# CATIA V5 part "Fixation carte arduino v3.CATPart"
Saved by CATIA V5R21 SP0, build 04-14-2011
Part number: Porte carte arduino
Bounding box of the stored display mesh (mm): x -6.9 to 25, y 0 to 105, z 0 to 59.3
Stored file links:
  C:\Users\2027.DESARCY-LEMIE30\Desktop\V16(05.04.2023)\Fixation carte arduino v3.CATPart
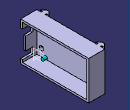
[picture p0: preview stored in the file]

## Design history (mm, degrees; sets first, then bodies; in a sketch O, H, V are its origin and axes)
Body1 (main body)
  Sketch1 on yz-plane, origin (0, 0, 0), H (0, 1, 0), V (0, 0, 1)
    line L1 (0, 0) -> (105, 0)
    line L2 (105, 0) -> (105, 59.3)
    line L3 (105, 59.3) -> (0, 59.3)
    line L4 (0, 59.3) -> (0, 0)
    length L3 = 105
    length L2 = 59.3
    horizontal: L1 H, L3 H
    vertical: L2 V, L4 V
  Pad1: profile Sketch1, direction (1, 0, 0), length 20
  Sketch2 on end face of Pad1, origin (20, 0, 0), H (0, 1, 0), V (0, 0, 1)
    line L1 (3, 3) -> (102, 3)
    line L2 (102, 3) -> (102, 56.3)
    line L3 (102, 56.3) -> (3, 56.3)
    line L4 (3, 56.3) -> (3, 3)
    reference projected line E1 (105, 0) -> (105, 59) from edge [face of Pad1 from Sketch1.L2 | end face of Pad1]
    reference projected line E2 (108.5, 59.3) -> (0, 59.3) from edge [face of Pad1 from Sketch1.L3 | end face of Pad1]
    reference projected line E3 (0, 59.3) -> (0, 0) from edge [face of Pad1 from Sketch1.L4 | end face of Pad1]
    reference projected line E4 (0, 0) -> (105, 0) from edge [face of Pad1 from Sketch1.L1 | end face of Pad1]
    distance L2 E1 = 3
    distance L3 E2 = 3
    distance L4 E3 = 3
    distance L1 E4 = 3
    horizontal: L1 H, L3 H
    vertical: L2 V, L4 V
  Pocket1: profile Sketch2, direction (-1, 0, 0), length 17
  Sketch3 on face of Pad1 from Sketch1.L3, origin (0, 0, 59.3), H (1, 0, 0), V (0, 1, 0)
    point P1 (0, 98.1)
    line L1 (0, 98.1) -> (-2, 98.1)
    point P2 (-2, 98.1)
    line L2 (-2, 98.1) -> (-2, 101.9)
    point P3 (-2, 101.9)
    line L3 (-2, 101.9) -> (-6.9, 97)
    point P4 (-6.9, 97)
    line L4 (-6.9, 97) -> (-6.9, 95.1)
    point P5 (-6.9, 95.1)
    construction line L5 (-42.3956, 95.1) -> (20, 95.1)
    point P7 (20, 95.1)
    reference projected line E1 (0, 105) -> (0, 0) from edge [start face of Pad1 | face of Pad1 from Sketch1.L3]
    reference projected line E2 (20, 105) -> (20, 0) from edge [face of Pad1 from Sketch1.L3 | end face of Pad1]
    point P8 (-6.9, 95.1)
    point P9 (-6.9, 93.2)
    line L6 (-6.9, 93.2) -> (-6.9, 95.1)
    point P10 (-2, 88.3)
    line L7 (-2, 88.3) -> (-6.9, 93.2)
    point P11 (-2, 92.1)
    line L8 (-2, 92.1) -> (-2, 88.3)
    point P12 (0, 92.1)
    line L9 (0, 92.1) -> (-2, 92.1)
    axis line L10 (-12.7576, 52.5) -> (34.0087, 52.5)
    line L11 (0, 98.1) -> (0, 92.1)
    point P15 (0, 6.9)
    point P16 (-2, 6.9)
    point P17 (-2, 3.1)
    point P18 (-6.9, 8)
    point P19 (-6.9, 9.9)
    point P20 (-6.9, 9.9)
    point P21 (-6.9, 11.8)
    point P22 (-2, 16.7)
    point P23 (-2, 12.9)
    point P24 (0, 12.9)
    line L12 (0, 6.9) -> (-2, 6.9)
    line L13 (-2, 6.9) -> (-2, 3.1)
    line L14 (-2, 3.1) -> (-6.9, 8)
    line L15 (-6.9, 8) -> (-6.9, 9.9)
    line L16 (-6.9, 11.8) -> (-6.9, 9.9)
    line L17 (-2, 16.7) -> (-6.9, 11.8)
    line L18 (-2, 12.9) -> (-2, 16.7)
    line L19 (0, 12.9) -> (-2, 12.9)
    line L20 (0, 6.9) -> (0, 12.9)
    reference projected line E3 (0, 105) -> (20, 105) from edge [face of Pad1 from Sketch1.L3 | face of Pad1 from Sketch1.L2]
    reference projected line E4 (0, 105) -> (20, 105) from edge [face of Pad1 from Sketch1.L3 | face of Pad1 from Sketch1.L2]
    distance L1 L5 = 3
    length L2 = 3.8
    angle L3 L2 = 45
    length L4 = 1.9
    distance L4 L11 = 6.9
    distance E3 L10 = 52.5
    distance L1 E4 = 6.9
    coincidence: P1 V, P5 L5, P1 E1, P7 E2, L4 L6, P5 P8
    horizontal: L1 H, L5 H, L10 H
    vertical: L2 V, L4 V, L11 V
    symmetry: P5 P8 L5, P4 P9 L5, L4 L6 L5, P3 P10 L5, L3 L7 L5, P2 P11 L5, L2 L8 L5, P1 P12 L5, L1 L9 L5, P1 P15 L10, P2 P16 L10, P3 P17 L10, P4 P18 L10, P5 P19 L10, P8 P20 L10, P9 P21 L10, P10 P22 L10, P11 P23 L10, P12 P24 L10, L1 L12 L10, L2 L13 L10, L3 L14 L10, L4 L15 L10, L6 L16 L10, L7 L17 L10, L8 L18 L10, L9 L19 L10, L11 L20 L10
  Pad2: profile Sketch3, direction (0, 0, -1), length 59
  Sketch4 on end face of Pocket1, origin (3, 16.9157, 27.9903), H (0, 1, 0), V (0, 0, 1)
    point P1 (78.1843, 16.2597)
    construction line L1 (35.5843, 31.3097) -> (35.5843, -27.9903)
    point P2 (35.5843, 31.3097)
    point P3 (35.5843, -27.9903)
    reference projected line E1 (88.0843, -27.9903) -> (88.0843, 31.0097) from edge [face of Pad1 from Sketch1.L2 | end face of Pad1]
    reference projected line E2 (91.5843, 31.3097) -> (-16.9157, 31.3097) from edge [face of Pad1 from Sketch1.L3 | end face of Pad1]
    reference projected line E3 (-16.9157, -27.9903) -> (88.0843, -27.9903) from edge [face of Pad1 from Sketch1.L1 | end face of Pad1]
    construction line L2 (35.5843, 1.6597) -> (88.0843, 1.6597)
    point P4 (35.5843, 1.6597)
    point P5 (88.0843, 1.6597)
    reference projected line E4 (88.0843, -27.9903) -> (88.0843, 31.0097) from edge [face of Pad1 from Sketch1.L2 | end face of Pad1]
    axis line L3 (78.1843, 1.6597) -> (78.1843, 30.8597)
    point P6 (78.1843, 1.6597)
    reference projected line E5 (88.0843, -27.9903) -> (88.0843, 31.3097) from edge [face of Pad1 from Sketch1.L2 | end face of Pad1]
    distance L1 E1 = 52.5
    distance P1 E5 = 9.9
    vertical: L1 V, L3 V
    coincidence: P2 E2, P3 E3, P5 E4, P6 L2
    horizontal: L2 H
    midpoint: P4 L1, P1 L3
  Hole1: placed by Sketch4, at (3, 95.1, 44.25) direction (-1, 0, 0), diameter 3.8, depth 12, counterbore diameter 6.8, counterbore depth 4
  RectPattern1: of Hole1, direction 1 instances 2, spacing 84.8, along start face of Pad1 reversed, direction 2 instances 2, spacing 29.5, along start face of Pad1
  Sketch5 on face of Pad1 from Sketch1.L4, origin (0, 0, 0), H (1, 0, 0), V (0, 0, 1)
    line L1 (9, 47.5) -> (20, 47.5)
    line L2 (20, 47.5) -> (20, 35.5)
    line L3 (20, 35.5) -> (9, 35.5)
    line L4 (9, 35.5) -> (9, 47.5)
    reference projected line E1 (20, 59.3) -> (20, 0) from edge [face of Pad1 from Sketch1.L4 | end face of Pad1]
    reference projected line E2 (0, 59.3) -> (20, 59.3) from edge [face of Pad1 from Sketch1.L4 | face of Pad1 from Sketch1.L3]
    line L5 (9, 15.8) -> (20, 15.8)
    line L6 (20, 15.8) -> (20, 6.8)
    line L7 (20, 6.8) -> (9, 6.8)
    line L8 (9, 6.8) -> (9, 15.8)
    reference projected line E3 (20, 59.3) -> (20, 0) from edge [face of Pad1 from Sketch1.L4 | end face of Pad1]
    reference projected line E4 (0, 59.3) -> (20, 59.3) from edge [face of Pad1 from Sketch1.L4 | face of Pad1 from Sketch1.L3]
    reference projected line E5 (0, 0) -> (20, 0) from edge [face of Pad1 from Sketch1.L1 | face of Pad1 from Sketch1.L4]
    reference projected point E6 (20, 56.3) from edge [end face of Pad1 | face of Pocket1 from Sketch2.L3]
    reference projected point E7 (20, 3) from edge [end face of Pad1 | face of Pocket1 from Sketch2.L1]
    length L1 = 11
    length L2 = 12
    distance L1 E2 = 11.8
    length L6 = 9
    length L5 = 11
    distance L3 L5 = 19.7
    distance E4 E5 = 59.3 (reference)
    distance E6 E7 = 53.3 (reference)
    horizontal: L1 H, L3 H, L5 H, L7 H
    vertical: L2 V, L4 V, L6 V, L8 V
    coincidence: E1 L2, E3 L6
  Pocket2: profile Sketch5, direction (0, 1, 0), through (limit type 6)
  Sketch6 on end face of Pocket1, origin (3, 0, 0), H (0, 1, 0), V (0, 0, 1)
    circle A1 centre (17, 5.5) radius 2.5
    point P1 (17, 5.5)
    circle A2 centre (91.9, 53.8) radius 2.5
    point P2 (91.9, 53.8)
    reference projected line E1 (3, 3) -> (102, 3) from edge [end face of Pad1 | face of Pocket1 from Sketch2.L1]
    reference projected line E2 (3, 56.3) -> (3, 3) from edge [end face of Pocket1 | face of Pocket1 from Sketch2.L4]
    radius A2 = 2.5
    radius A1 = 2.5
    distance P1 P2 H = 74.9
    distance P2 P1 V = 48.3
    distance P1 E1 = 2.5
    distance P1 E2 = 14
  Pad3: profile Sketch6, direction (1, 0, 0), length 5
  Pad4: profile end face of Pad1, direction along end face of Pad1, length 5, opposite side length 2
